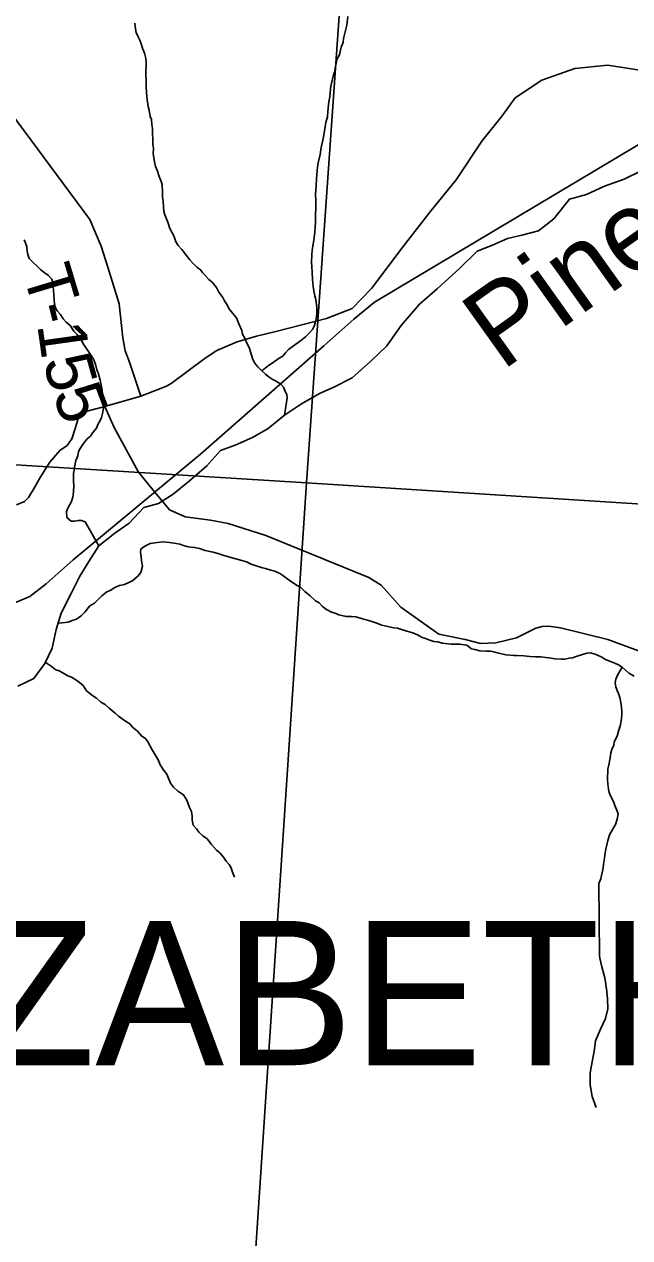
# Model space of a CAD drawing. Extents: x 0 to 34, y 0 to 22.
# Drawn here: x 6.055 to 6.769, y 16.547 to 17.98 of the extents above; entities that cross this region are included whole.
import ezdxf

# ---------------------------------------------------------------- set-up
doc = ezdxf.new("R2010")
doc.units = 0
for name, color, linetype in [('GM_X_County_Road', 7, 'Continuous'), ('GM_X_Minor_River', 7, 'Continuous'), ('GM_X_Minor_River_Text', 7, 'Continuous'), ('GM_X_Rail_Line', 7, 'Continuous'), ('GM_X_Section', 7, 'Continuous'), ('GM_X_Township_Road', 7, 'Continuous'), ('GM_X_Township_Road_Text', 7, 'Continuous'), ('GM_X_Township_Text', 7, 'Continuous')]:
    doc.layers.add(name, color=color, linetype=linetype)

msp = doc.modelspace()

# ---------------------------------------------------------------- linework, layer by layer
at = {"layer": 'GM_X_County_Road'}
msp.add_line((6.1501, 17.5287), (6.1925, 17.5411), dxfattribs=at)
for points in [[(6.1925, 17.5411), (6.2229, 17.5528), (6.2283, 17.5561), (6.2682, 17.5859), (6.2822, 17.5948), (6.2931, 17.5995), (6.3063, 17.6051), (6.3289, 17.6117), (6.3519, 17.6175), (6.4116, 17.6328), (6.4417, 17.6447), (6.4647, 17.668), (6.5022, 17.7177), (6.5351, 17.7602), (6.5647, 17.7967), (6.595, 17.8422), (6.6189, 17.8722), (6.6344, 17.8934), (6.6658, 17.9143), (6.7045, 17.928), (6.7435, 17.9318), (6.7985, 17.9234)], [(6.0456, 17.4126), (6.0551, 17.4168), (6.0598, 17.4214), (6.0664, 17.4324), (6.0736, 17.4449), (6.0849, 17.4629), (6.0968, 17.4767), (6.1054, 17.4829), (6.1112, 17.4907), (6.1149, 17.5027), (6.1198, 17.5183), (6.1252, 17.5223), (6.1336, 17.5244), (6.1501, 17.5287)]]:
    msp.add_lwpolyline(points, dxfattribs=at)
at = {"layer": 'GM_X_Minor_River'}
for points in [[(6.3352, 17.5708), (6.3432, 17.5772), (6.3474, 17.5802), (6.3555, 17.5858), (6.3601, 17.5884), (6.3631, 17.5921), (6.3666, 17.5963), (6.3754, 17.6026), (6.3807, 17.6064), (6.3869, 17.6112), (6.3915, 17.6157), (6.3949, 17.6199), (6.3969, 17.6236), (6.3981, 17.6278), (6.3993, 17.6323), (6.4001, 17.6384), (6.4002, 17.6452), (6.3998, 17.649), (6.3988, 17.6551), (6.3977, 17.6597), (6.3966, 17.6654), (6.3959, 17.6704), (6.3956, 17.6746), (6.3952, 17.6791), (6.3946, 17.6871), (6.3943, 17.6943), (6.394, 17.6989), (6.3941, 17.7084), (6.3945, 17.7129), (6.3957, 17.7209), (6.3965, 17.7251), (6.3978, 17.7349), (6.3982, 17.7406), (6.3987, 17.7471), (6.399, 17.7718), (6.3987, 17.7794), (6.3991, 17.7839), (6.3992, 17.7896), (6.3997, 17.798), (6.4009, 17.8113), (6.4018, 17.8166), (6.4042, 17.8264), (6.4054, 17.8348), (6.4082, 17.8469), (6.4107, 17.8643), (6.4126, 17.8711), (6.4131, 17.8772), (6.4144, 17.8886), (6.4156, 17.8947), (6.416, 17.8985), (6.4161, 17.9042), (6.4172, 17.9087), (6.4197, 17.9205), (6.4212, 17.925), (6.4216, 17.9288), (6.424, 17.9394), (6.4268, 17.9443), (6.4288, 17.953), (6.4311, 17.9587), (6.4315, 17.9636), (6.4343, 17.9746), (6.4355, 17.9791), (6.4368, 17.9894)], [(6.362, 17.5184), (6.3652, 17.5389), (6.3648, 17.5427), (6.3622, 17.5477), (6.3608, 17.5515), (6.3578, 17.5554), (6.3514, 17.5592), (6.3476, 17.5612), (6.3438, 17.5635), (6.3397, 17.567), (6.3352, 17.5708), (6.3307, 17.5755), (6.3266, 17.5804), (6.3244, 17.5854), (6.3222, 17.5923), (6.3203, 17.5984), (6.3174, 17.6037), (6.3152, 17.6095), (6.3126, 17.6144), (6.3118, 17.6186), (6.3081, 17.6263), (6.3052, 17.6335), (6.3011, 17.6385), (6.2962, 17.6447), (6.2944, 17.6489), (6.291, 17.6535), (6.2892, 17.6577), (6.2843, 17.6638), (6.2817, 17.6695), (6.2765, 17.6757), (6.2727, 17.6788), (6.269, 17.6826), (6.2652, 17.6869), (6.2626, 17.6907), (6.2588, 17.693), (6.254, 17.698), (6.2502, 17.7022), (6.2461, 17.7076), (6.2409, 17.7141), (6.2364, 17.7188), (6.2338, 17.7233), (6.2312, 17.7302), (6.2267, 17.739), (6.2242, 17.7466), (6.2209, 17.755), (6.2194, 17.7592), (6.2188, 17.771), (6.2181, 17.7764), (6.2181, 17.7817), (6.2175, 17.7912), (6.216, 17.7958), (6.2142, 17.8003), (6.2123, 17.8068), (6.2097, 17.8122), (6.2087, 17.8179), (6.2076, 17.8228), (6.2069, 17.8274), (6.2073, 17.8335), (6.2066, 17.8384), (6.2067, 17.8438), (6.2064, 17.8517), (6.2061, 17.8571), (6.2054, 17.862), (6.2051, 17.8677), (6.2036, 17.8715), (6.2022, 17.8788), (6.2011, 17.883), (6.2, 17.8913), (6.199, 17.8993), (6.1987, 17.9073), (6.1988, 17.9141), (6.1985, 17.9202), (6.1987, 17.9354), (6.1983, 17.94), (6.1969, 17.9461), (6.1943, 17.9522), (6.1932, 17.956), (6.1914, 17.9614), (6.1891, 17.9652), (6.1869, 17.9705), (6.1862, 17.9747), (6.1855, 17.9816)], [(6.7822, 17.8066), (6.7628, 17.7972), (6.7397, 17.789), (6.7183, 17.7792), (6.6982, 17.7736), (6.6799, 17.7506), (6.6619, 17.7362), (6.6422, 17.731), (6.6251, 17.7273), (6.6076, 17.7194), (6.5893, 17.7123), (6.5687, 17.6919), (6.542, 17.6678), (6.5214, 17.6497), (6.4996, 17.6243), (6.4828, 17.6005), (6.4637, 17.5824), (6.442, 17.5627), (6.4203, 17.5515), (6.4032, 17.544), (6.3822, 17.5319), (6.362, 17.5184), (6.3426, 17.5029), (6.3243, 17.4924), (6.3038, 17.4833), (6.2863, 17.477), (6.2702, 17.4588)], [(6.1428, 17.3645), (6.143, 17.3642), (6.1268, 17.3926), (6.1226, 17.3942), (6.1184, 17.3943), (6.1142, 17.3936), (6.1101, 17.3936), (6.1052, 17.3979), (6.1049, 17.4047), (6.1068, 17.4096), (6.1103, 17.416), (6.1123, 17.4217), (6.1131, 17.4281), (6.1132, 17.4357), (6.1129, 17.4407), (6.113, 17.4494), (6.1142, 17.4566), (6.1158, 17.465), (6.1182, 17.4706), (6.119, 17.4756), (6.1209, 17.4793), (6.1248, 17.485), (6.129, 17.4906), (6.1329, 17.4936), (6.1356, 17.4982), (6.1402, 17.5034), (6.1417, 17.5076), (6.1444, 17.5121), (6.146, 17.5159), (6.1472, 17.5204), (6.1484, 17.5269), (6.1481, 17.5322), (6.1474, 17.5379), (6.1471, 17.5432), (6.1468, 17.5482), (6.1457, 17.5539), (6.1446, 17.56), (6.1421, 17.5684), (6.1406, 17.5722), (6.1388, 17.579), (6.1366, 17.5848), (6.1332, 17.5901), (6.1299, 17.5951), (6.125, 17.6016), (6.1228, 17.6058), (6.1175, 17.6139), (6.1134, 17.6177), (6.1089, 17.6243), (6.1044, 17.6285), (6.1007, 17.6323), (6.0977, 17.6373), (6.0936, 17.6419), (6.0914, 17.6461), (6.0907, 17.6503), (6.0903, 17.6545), (6.0896, 17.6606), (6.0893, 17.6659), (6.089, 17.6705), (6.0887, 17.675), (6.0876, 17.6792), (6.0834, 17.6835), (6.0782, 17.687), (6.0744, 17.6904), (6.0703, 17.6943), (6.065, 17.6993), (6.0605, 17.7035), (6.0591, 17.7085), (6.0584, 17.7123), (6.058, 17.7172), (6.0566, 17.721), (6.0547, 17.7256)], [(6.2702, 17.4588), (6.2497, 17.4411), (6.2306, 17.4253), (6.2134, 17.4143), (6.196, 17.4095), (6.1788, 17.391), (6.1616, 17.3793), (6.143, 17.3642), (6.1311, 17.3457), (6.1203, 17.3283), (6.1107, 17.3089), (6.0984, 17.2847), (6.0926, 17.2654), (6.0879, 17.2434), (6.0791, 17.2252), (6.0661, 17.2078), (6.0474, 17.1984)], [(6.0951, 17.2729), (6.0996, 17.2733), (6.1068, 17.274), (6.1114, 17.2762), (6.1167, 17.2776), (6.1221, 17.2818), (6.1263, 17.2859), (6.1324, 17.2934), (6.1378, 17.2964), (6.142, 17.3009), (6.1466, 17.3054), (6.1524, 17.3099), (6.1562, 17.3117), (6.1619, 17.3151), (6.1672, 17.3173), (6.1733, 17.3187), (6.179, 17.3213), (6.1829, 17.3232), (6.1894, 17.3288), (6.1925, 17.3329), (6.1944, 17.3401), (6.1934, 17.3466), (6.1927, 17.3511), (6.192, 17.3569), (6.1924, 17.3606), (6.1981, 17.3644), (6.2035, 17.367), (6.2088, 17.3677), (6.2153, 17.3687), (6.2194, 17.369), (6.2262, 17.3682), (6.2342, 17.367), (6.2384, 17.3661), (6.2429, 17.3646), (6.2482, 17.363), (6.2558, 17.3625), (6.2615, 17.3613), (6.2683, 17.3589), (6.2777, 17.3569), (6.2849, 17.3549), (6.2891, 17.3533), (6.2985, 17.3506), (6.303, 17.3494), (6.3117, 17.347), (6.317, 17.3454), (6.3227, 17.3427), (6.3287, 17.3407), (6.3359, 17.3383), (6.3397, 17.3375), (6.3458, 17.3355), (6.3507, 17.3343), (6.3563, 17.3316), (6.3601, 17.3293), (6.3691, 17.3227), (6.377, 17.3173), (6.3808, 17.3153), (6.3861, 17.3103), (6.3924, 17.3053), (6.3985, 17.2995), (6.403, 17.2968), (6.4067, 17.2926), (6.4116, 17.2891), (6.4176, 17.286), (6.4218, 17.2848), (6.426, 17.2828), (6.4347, 17.2808), (6.4411, 17.2807), (6.446, 17.2803), (6.4528, 17.2783), (6.4638, 17.2755), (6.4699, 17.2732), (6.477, 17.2704), (6.4838, 17.2692), (6.491, 17.2676), (6.4952, 17.2671), (6.5001, 17.2655), (6.5092, 17.2628), (6.5133, 17.2616), (6.519, 17.2592), (6.5243, 17.2561), (6.5284, 17.2549), (6.5322, 17.2534), (6.5383, 17.2514), (6.5428, 17.251), (6.5481, 17.2494), (6.5587, 17.2481), (6.569, 17.248), (6.5773, 17.2471), (6.5826, 17.2428), (6.5867, 17.242), (6.5924, 17.2404), (6.6004, 17.24), (6.6049, 17.2399), (6.6091, 17.2391), (6.6147, 17.2375), (6.6234, 17.2355), (6.6325, 17.2346), (6.6363, 17.2349), (6.6443, 17.2345), (6.6515, 17.2336)], [(6.0796, 17.2269), (6.0853, 17.223), (6.0921, 17.2179), (6.0959, 17.2167), (6.1023, 17.2132), (6.1064, 17.2109), (6.1106, 17.2093), (6.1144, 17.207), (6.12, 17.2028), (6.1245, 17.1993), (6.1282, 17.1932), (6.1358, 17.187), (6.1403, 17.1843), (6.1452, 17.1796), (6.1504, 17.1769), (6.1549, 17.1727), (6.1621, 17.1665), (6.1662, 17.163), (6.1745, 17.1572), (6.1794, 17.1541), (6.1828, 17.1503), (6.1884, 17.1453), (6.1936, 17.1395), (6.1978, 17.1368), (6.2008, 17.133), (6.206, 17.1234), (6.2104, 17.1154), (6.213, 17.1115), (6.2153, 17.1058), (6.2197, 17.0989), (6.2231, 17.0947), (6.2275, 17.084), (6.2309, 17.0794), (6.2361, 17.0744), (6.2429, 17.0701), (6.2466, 17.064), (6.25, 17.0552), (6.2522, 17.0506), (6.2529, 17.0449), (6.2532, 17.0403), (6.2543, 17.0343), (6.258, 17.03), (6.261, 17.0262), (6.2655, 17.0216), (6.2708, 17.0181), (6.276, 17.0116), (6.2816, 17.0047), (6.2858, 17.0016), (6.2899, 16.9966), (6.2932, 16.992), (6.2966, 16.9881), (6.2992, 16.9839), (6.3007, 16.979), (6.3031, 16.9729)], [(6.6515, 17.2336), (6.6583, 17.2331), (6.6644, 17.2331), (6.6705, 17.2326), (6.6742, 17.2322), (6.6811, 17.231), (6.6886, 17.2305), (6.6928, 17.2304), (6.6981, 17.2315), (6.7019, 17.2322), (6.7061, 17.2337), (6.7149, 17.2362), (6.7191, 17.2377), (6.7229, 17.238), (6.7285, 17.2364), (6.7357, 17.2333), (6.741, 17.2302), (6.7519, 17.2259), (6.7561, 17.2239), (6.7606, 17.2208), (6.7685, 17.2139), (6.7745, 17.2104)], [(6.7606, 17.2208), (6.7548, 17.2114), (6.7529, 17.2069), (6.7524, 17.2023), (6.7531, 17.1977), (6.7546, 17.1935), (6.7561, 17.1897), (6.7579, 17.1851), (6.759, 17.1794), (6.7597, 17.1737), (6.76, 17.1688), (6.76, 17.165), (6.7595, 17.1604), (6.7587, 17.1528), (6.7563, 17.1453), (6.7544, 17.1396), (6.7512, 17.1328), (6.7508, 17.129), (6.7481, 17.1237), (6.7473, 17.1199), (6.7465, 17.1139), (6.7449, 17.1055), (6.7437, 17.101), (6.7436, 17.0964), (6.7432, 17.0926), (6.7431, 17.0881), (6.7435, 17.0831), (6.7442, 17.077), (6.7452, 17.0728), (6.7471, 17.0683), (6.7501, 17.0625), (6.7519, 17.0576), (6.7545, 17.0511), (6.7556, 17.0473), (6.7544, 17.0416), (6.7528, 17.0351), (6.7501, 17.0314), (6.7481, 17.0276), (6.7458, 17.0238), (6.7435, 17.0163), (6.7423, 17.0113), (6.7411, 17.006), (6.7402, 16.9992), (6.7398, 16.9954), (6.7386, 16.9882), (6.7381, 16.984), (6.7373, 16.9802), (6.7361, 16.9749), (6.7353, 16.9711), (6.733, 16.9655), (6.7336, 16.8804)], [(6.7336, 16.8804), (6.7341, 16.8772), (6.7363, 16.8669), (6.7401, 16.854), (6.742, 16.8411), (6.7431, 16.8298), (6.7435, 16.8176), (6.7408, 16.8062), (6.7348, 16.7933), (6.7291, 16.7797), (6.7276, 16.7676), (6.725, 16.755), (6.7227, 16.7418), (6.7227, 16.7277), (6.7249, 16.7141), (6.7299, 16.7008)]]:
    msp.add_lwpolyline(points, dxfattribs=at)
at = {"layer": 'GM_X_Rail_Line'}
msp.add_lwpolyline([(6.9911, 17.9641), (6.4682, 17.6519), (6.444, 17.6319), (6.4086, 17.6005), (6.263, 17.4725), (6.1126, 17.3479), (6.0808, 17.3194), (6.0614, 17.3045), (6.0277, 17.2904)], dxfattribs=at)
at = {"layer": 'GM_X_Section'}
for points in [[(5.4469, 18.529), (6.4594, 18.4632), (6.388, 17.4386), (5.3838, 17.5009)], [(6.4594, 18.4632), (7.4583, 18.399), (7.3907, 17.3751), (6.388, 17.4386)], [(5.3838, 17.5009), (6.388, 17.4386), (6.3205, 16.4222), (5.3178, 16.4777)], [(6.388, 17.4386), (7.3907, 17.3751), (7.3221, 16.3607), (6.3205, 16.4222)]]:
    msp.add_lwpolyline(points, close=True, dxfattribs=at)
at = {"layer": 'GM_X_Township_Road'}
msp.add_line((6.1501, 17.5287), (6.1925, 17.5411), dxfattribs=at)
for points in [[(6.1533, 17.6932), (6.1455, 17.7183), (6.1321, 17.7496), (6.031, 17.8864), (5.9649, 17.9774), (5.8325, 18.118), (5.6892, 18.2779), (5.5706, 18.3854), (5.4769, 18.4764), (5.3776, 18.6004)], [(6.1925, 17.5411), (6.1791, 17.5812), (6.1739, 17.5946), (6.1713, 17.6101), (6.1667, 17.65), (6.1533, 17.6932)], [(6.7872, 17.2377), (6.7434, 17.2538), (6.6877, 17.2675), (6.674, 17.2694), (6.6662, 17.2689), (6.6584, 17.2669), (6.6356, 17.2555), (6.6113, 17.2496), (6.5932, 17.2491), (6.5751, 17.2535), (6.5441, 17.2599), (6.4992, 17.2917), (6.4761, 17.3177), (6.4616, 17.3269), (6.34, 17.3763), (6.2956, 17.3907), (6.2746, 17.3944), (6.2449, 17.3985), (6.2264, 17.4067), (6.2091, 17.4277), (6.1898, 17.4512), (6.161, 17.504), (6.1501, 17.5287)]]:
    msp.add_lwpolyline(points, dxfattribs=at)

# ---------------------------------------------------------------- texts
at = {"layer": 'GM_X_Minor_River_Text'}
msp.add_text('Pine', height=0.09469, rotation=35.4888, dxfattribs=at).set_placement((6.6183, 17.57))
at = {"layer": 'GM_X_Township_Road_Text'}
for s, rotation, p in [('T', 286.7366, (6.0528, 17.6865)), ('-', 283.7617, (6.0648, 17.6465)), ('1', 277.9826, (6.0701, 17.6254)), ('5', 285.466, (6.0766, 17.5828)), ('5', 290.722, (6.0877, 17.5436))]:
    msp.add_text(s, height=0.0568, rotation=rotation, dxfattribs=at).set_placement(p)
at = {"layer": 'GM_X_Township_Text'}
msp.add_text('ELIZABETH', height=0.17045, rotation=0, dxfattribs=at).set_placement((5.6574, 16.7509))

doc.saveas('drawing.dxf')
